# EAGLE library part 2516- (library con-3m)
3M (TM) Pak 100 4-Wall Header Source: 3M
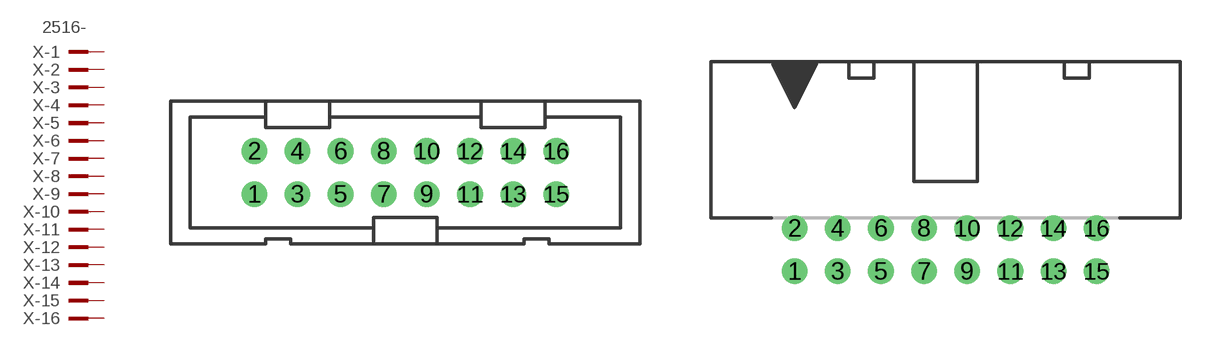
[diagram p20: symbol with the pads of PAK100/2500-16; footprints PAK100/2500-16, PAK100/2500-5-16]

Designator prefix X; gates -1=PINV -2=PIN -3=PIN -4=PIN -5=PIN -6=PIN -7=PIN -8=PIN -9=PIN -10=PIN -11=PIN -12=PIN -13=PIN -14=PIN -15=PIN -16=PIN

## 2516- (OC_FARNELL: unknown; OC_NEWARK: unknown)  [PAK100/2500-16]
1  -1:KL  pas
2  -2:KL  pas
3  -3:KL  pas
4  -4:KL  pas
5  -5:KL  pas
6  -6:KL  pas
7  -7:KL  pas
8  -8:KL  pas
9  -9:KL  pas
10  -10:KL  pas
11  -11:KL  pas
12  -12:KL  pas
13  -13:KL  pas
14  -14:KL  pas
15  -15:KL  pas
16  -16:KL  pas

## 2516-5 (MPN: D2516-5002-AR; OC_FARNELL: 9838376; OC_NEWARK: 12P7055)  [PAK100/2500-5-16]
Pads as for PAK100/2500-16

## Footprint PAK100/2500-16 (pad centres in mm)
3M (TM) Pak 100 4-Wall Header Straight Source: 3M
drill 1 pad 1.422 round: 1 -8.89,-1.27; 2 -8.89,1.27; 3 -6.35,-1.27; 4 -6.35,1.27; 5 -3.81,-1.27; 6 -3.81,1.27; 7 -1.27,-1.27; 8 -1.27,1.27; 9 1.27,-1.27; 10 1.27,1.27; 11 3.81,-1.27; 12 3.81,1.27; 13 6.35,-1.27; 14 6.35,1.27; 15 8.89,-1.27; 16 8.89,1.27

## Footprint PAK100/2500-5-16 (pad centres in mm)
3M (TM) Pak 100 4-Wall Header Right Angle Source: 3M
drill 1 pad 1.422 round: 1 -8.89,-1.27; 2 -8.89,1.27; 3 -6.35,-1.27; 4 -6.35,1.27; 5 -3.81,-1.27; 6 -3.81,1.27; 7 -1.27,-1.27; 8 -1.27,1.27; 9 1.27,-1.27; 10 1.27,1.27; 11 3.81,-1.27; 12 3.81,1.27; 13 6.35,-1.27; 14 6.35,1.27; 15 8.89,-1.27; 16 8.89,1.27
